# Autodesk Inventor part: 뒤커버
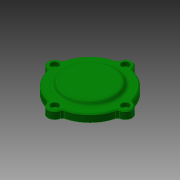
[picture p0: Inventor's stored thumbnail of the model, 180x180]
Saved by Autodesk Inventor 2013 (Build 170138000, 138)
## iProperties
Company: 한국ATC센터
Created: 2015-12
Part Number: 뒤커버
Document SubType Name: Modeling
Designer: mdu
Density: 2.71 g/cm^3
Material: 알루미늄 6061
Author: mdu
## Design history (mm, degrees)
sketch "스케치1"
  geometry: C1 r 1.621 at (0, 6.75) reference; C2 r 1.621 at (-37, -30.25) reference; C3 r 1.621 at (0, -67.25) reference; C4 r 1.621 at (37, -30.25) reference; C5 r 10 at (0, -30.25) reference; C6 r 12 at (0, -30.25); C7 r 24.5 at (0, -30.25) reference; A1 r 3 centre (-38.77, -20.408) between (-38.239, -23.361) and (-35.862, -21.146) reference; A2 r 7 centre (-37, -30.25) between (-38.239, -23.361) and (-38.239, -37.139) reference; A3 r 3 centre (-38.77, -40.092) between (-35.862, -39.354) and (-38.239, -37.139) reference; A4 r 37 centre (0, -30.25) between (-35.862, -39.354) and (-9.104, -66.113) reference; A5 r 3 centre (-9.842, -69.02) between (-6.889, -68.489) and (-9.104, -66.113) reference; A6 r 7 centre (0, -67.25) between (-6.889, -68.489) and (6.889, -68.489) reference; A7 r 3 centre (9.842, -69.02) between (9.104, -66.112) and (6.889, -68.489) reference; A8 r 37 centre (0, -30.25) between (9.104, -66.112) and (35.863, -39.354) reference; A9 r 3 centre (38.77, -40.092) between (38.239, -37.139) and (35.863, -39.354) reference; A10 r 7 centre (37, -30.25) between (38.239, -37.139) and (38.239, -23.361) reference; A11 r 3 centre (38.77, -20.408) between (35.863, -21.146) and (38.239, -23.361) reference; A12 r 37 centre (0, -30.25) between (35.863, -21.146) and (9.104, 5.612) reference; A13 r 3 centre (9.842, 8.52) between (6.889, 7.989) and (9.104, 5.612) reference; A14 r 7 centre (0, 6.75) between (6.889, 7.989) and (-6.889, 7.989) reference; A15 r 3 centre (-9.842, 8.52) between (-9.104, 5.612) and (-6.889, 7.989) reference; A16 r 37 centre (0, -30.25) between (-9.104, 5.612) and (-35.862, -21.146) reference; 1 further point
  constraints: 1 centre point, 1 coincident
  dimensions: "d2" = 2 radial gap between concentric circles of C6 C5
extrude "돌출1" new body sketch "스케치1" distance "d0" = 8; taper "d1" = 0 deg
sketch "스케치2"
  geometry: C1 r 23.5 at (0, -30.25) reference; C2 r 12 at (0, -30.25) reference; 1 further point
extrude "돌출2" join sketch "스케치2" distance "d4" = 6; taper "d5" = 0 deg
sketch "스케치9"
  geometry: C1 r 23.5 at (0, 0) reference; C2 r 21 at (0, 0); 1 further point
  constraints: 1 centre point, 1 coincident
  dimensions: "d61" = 42 diameter of C2
extrude "돌출6" cut sketch "스케치9" distance "d62" = 3; taper "d63" = 0 deg
node "작업 평면1"
sketch "스케치4"
  geometry: C1 r 12 at (0, -30.25) reference; C2 r 27 at (0, -30.25); 1 further point
  constraints: 1 centre point
  dimensions: "d10" = 15 radial gap between concentric circles of C1 C2
extrude "돌출4" join sketch "스케치4" distance "d11" = 4; taper "d12" = -20 deg
fillet "모깎기2" dims "d13" = 3
node "작업점1"
  node "작업축1"
chamfer "모따기2" distance "d24" = 1; stored, may be unused: second distance "d25" = 2, angle "d26" = 45 deg
hole "구멍6" diameter "d43" = 4.5; stored, may be unused: countersink angle "d47" = 90 deg, drill point angle "d49" = 118 deg; dims "d41" = 10, "d42" = 10, "d44" = 6, "d45" = 8, "d46" = 4.4, "d48" = 8
fillet "모깎기4" dims "d60" = 3
node "솔리드1"
pattern_circular "원형 패턴1" dims angle "d51" = 360 deg
node "참조1"
node "참조2"
